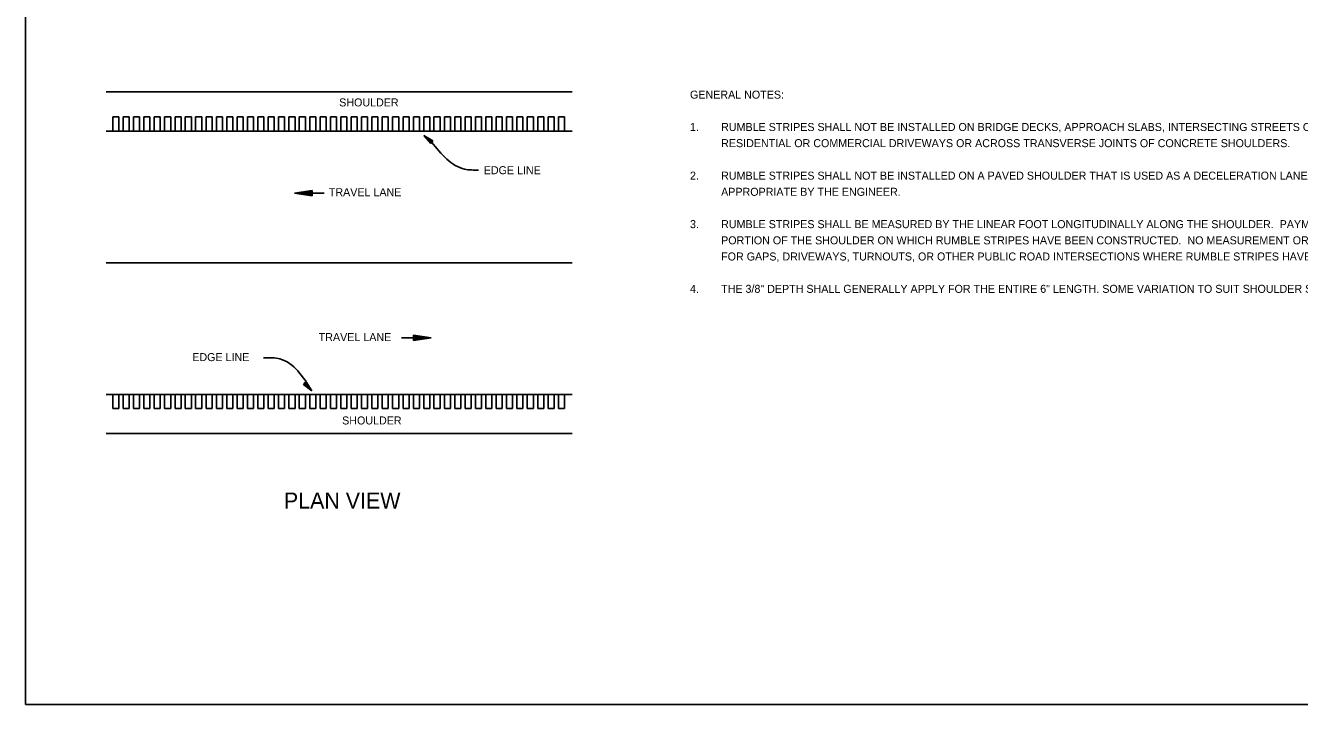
# Model space of a CAD drawing. Extents: x 28704 to 32542, y 50360 to 59122.
# Drawn here: x 28704 to 29736, y 50372 to 50922 of the extents above; entities that cross this region are included whole.
import ezdxf

# ---------------------------------------------------------------- set-up
doc = ezdxf.new("R2010")
doc.units = 0
doc.layers.add('Default', color=7, linetype='Continuous')

msp = doc.modelspace()

# ---------------------------------------------------------------- linework, layer by layer
at = {"layer": 'Default'}
for p, q in [((28769.2, 50868.5), (29146.9, 50868.5)), ((28774.7, 50836.8), (28774.7, 50848.3)), ((28774.7, 50848.3), (28779.6, 50848.3)), ((28779.6, 50836.8), (28779.6, 50848.3)), ((28783.1, 50836.8), (28783.1, 50848.3)), ((28783.1, 50848.3), (28788, 50848.3)), ((28788, 50836.8), (28788, 50848.3)), ((28791.5, 50836.8), (28791.5, 50848.3)), ((28791.5, 50848.3), (28796.4, 50848.3)), ((28796.4, 50836.8), (28796.4, 50848.3)), ((28799.9, 50836.8), (28799.9, 50848.3)), ((28799.9, 50848.3), (28804.8, 50848.3)), ((28804.8, 50836.8), (28804.8, 50848.3)), ((28808.3, 50836.8), (28808.3, 50848.3)), ((28808.3, 50848.3), (28813.2, 50848.3)), ((28813.2, 50836.8), (28813.2, 50848.3)), ((28816.7, 50836.8), (28816.7, 50848.3)), ((28816.7, 50848.3), (28821.6, 50848.3)), ((28821.6, 50836.8), (28821.6, 50848.3)), ((28825.1, 50836.8), (28825.1, 50848.3)), ((28825.1, 50848.3), (28830, 50848.3)), ((28830, 50836.8), (28830, 50848.3)), ((28833.4, 50836.8), (28833.4, 50848.3)), ((28833.4, 50848.3), (28838.4, 50848.3)), ((28838.4, 50836.8), (28838.4, 50848.3)), ((28841.8, 50836.8), (28841.8, 50848.3)), ((28841.8, 50848.3), (28846.8, 50848.3)), ((28846.8, 50836.8), (28846.8, 50848.3)), ((28850.2, 50836.8), (28850.2, 50848.3)), ((28850.2, 50848.3), (28855.2, 50848.3)), ((28855.2, 50836.8), (28855.2, 50848.3)), ((28858.6, 50836.8), (28858.6, 50848.3)), ((28858.6, 50848.3), (28863.5, 50848.3)), ((28863.5, 50836.8), (28863.5, 50848.3)), ((28867, 50836.8), (28867, 50848.3)), ((28867, 50848.3), (28871.9, 50848.3)), ((28871.9, 50836.8), (28871.9, 50848.3)), ((28875.4, 50836.8), (28875.4, 50848.3)), ((28875.4, 50848.3), (28880.3, 50848.3)), ((28880.3, 50836.8), (28880.3, 50848.3)), ((28883.8, 50836.8), (28883.8, 50848.3)), ((28883.8, 50848.3), (28888.7, 50848.3)), ((28888.7, 50836.8), (28888.7, 50848.3)), ((28892.2, 50836.8), (28892.2, 50848.3)), ((28892.2, 50848.3), (28897.1, 50848.3)), ((28897.1, 50836.8), (28897.1, 50848.3)), ((28900.6, 50836.8), (28900.6, 50848.3)), ((28900.6, 50836.8), (28900.6, 50848.3)), ((28900.6, 50848.3), (28905.5, 50848.3)), ((28905.5, 50836.8), (28905.5, 50848.3)), ((28909, 50836.8), (28909, 50848.3)), ((28909, 50848.3), (28913.9, 50848.3)), ((28913.9, 50836.8), (28913.9, 50848.3)), ((28917.4, 50836.8), (28917.4, 50848.3)), ((28917.4, 50848.3), (28922.3, 50848.3)), ((28922.3, 50836.8), (28922.3, 50848.3)), ((28925.8, 50836.8), (28925.8, 50848.3)), ((28925.8, 50848.3), (28930.7, 50848.3)), ((28930.7, 50836.8), (28930.7, 50848.3)), ((28934.2, 50836.8), (28934.2, 50848.3)), ((28934.2, 50848.3), (28939.1, 50848.3)), ((28939.1, 50836.8), (28939.1, 50848.3)), ((28942.6, 50836.8), (28942.6, 50848.3)), ((28942.6, 50848.3), (28947.5, 50848.3)), ((28947.5, 50836.8), (28947.5, 50848.3)), ((28951, 50836.8), (28951, 50848.3)), ((28951, 50848.3), (28955.9, 50848.3)), ((28955.9, 50836.8), (28955.9, 50848.3)), ((28959.4, 50836.8), (28959.4, 50848.3)), ((28959.4, 50848.3), (28964.3, 50848.3)), ((28964.3, 50836.8), (28964.3, 50848.3)), ((28967.8, 50836.8), (28967.8, 50848.3)), ((28967.8, 50848.3), (28972.7, 50848.3)), ((28972.7, 50836.8), (28972.7, 50848.3)), ((28976.2, 50836.8), (28976.2, 50848.3)), ((28976.2, 50848.3), (28981.1, 50848.3)), ((28981.1, 50836.8), (28981.1, 50848.3)), ((28984.6, 50836.8), (28984.6, 50848.3)), ((28984.6, 50848.3), (28989.5, 50848.3)), ((28989.5, 50836.8), (28989.5, 50848.3)), ((28993, 50836.8), (28993, 50848.3)), ((28993, 50848.3), (28997.9, 50848.3)), ((28997.9, 50836.8), (28997.9, 50848.3)), ((29001.4, 50836.8), (29001.4, 50848.3)), ((29001.4, 50848.3), (29006.3, 50848.3)), ((29006.3, 50836.8), (29006.3, 50848.3)), ((29009.8, 50836.8), (29009.8, 50848.3)), ((29009.8, 50848.3), (29014.7, 50848.3)), ((29014.7, 50836.8), (29014.7, 50848.3)), ((29018.2, 50836.8), (29018.2, 50848.3)), ((29018.2, 50848.3), (29023.1, 50848.3)), ((29023.1, 50836.8), (29023.1, 50848.3)), ((29026.6, 50836.8), (29026.6, 50848.3)), ((29026.6, 50848.3), (29031.5, 50848.3)), ((29031.5, 50836.8), (29031.5, 50848.3)), ((29034.9, 50836.8), (29034.9, 50848.3)), ((29034.9, 50848.3), (29039.9, 50848.3)), ((29039.9, 50836.8), (29039.9, 50848.3)), ((29043.3, 50836.8), (29043.3, 50848.3)), ((29043.3, 50848.3), (29048.3, 50848.3)), ((29048.3, 50836.8), (29048.3, 50848.3)), ((29051.7, 50836.8), (29051.7, 50848.3)), ((29051.7, 50848.3), (29056.7, 50848.3)), ((29056.7, 50836.8), (29056.7, 50848.3)), ((29060.1, 50836.8), (29060.1, 50848.3)), ((29060.1, 50848.3), (29065, 50848.3)), ((29065, 50836.8), (29065, 50848.3)), ((29068.5, 50836.8), (29068.5, 50848.3)), ((29068.5, 50848.3), (29073.4, 50848.3)), ((29073.4, 50836.8), (29073.4, 50848.3)), ((29076.9, 50836.8), (29076.9, 50848.3)), ((29076.9, 50848.3), (29081.8, 50848.3)), ((29081.8, 50836.8), (29081.8, 50848.3)), ((29085.3, 50836.8), (29085.3, 50848.3)), ((29085.3, 50848.3), (29090.2, 50848.3)), ((29090.2, 50836.8), (29090.2, 50848.3)), ((29093.7, 50836.8), (29093.7, 50848.3)), ((29093.7, 50848.3), (29098.6, 50848.3)), ((29098.6, 50836.8), (29098.6, 50848.3)), ((29102.1, 50836.8), (29102.1, 50848.3)), ((29102.1, 50848.3), (29107, 50848.3)), ((29107, 50836.8), (29107, 50848.3)), ((29110.5, 50836.8), (29110.5, 50848.3)), ((29110.5, 50848.3), (29115.4, 50848.3)), ((29115.4, 50836.8), (29115.4, 50848.3)), ((29118.9, 50836.8), (29118.9, 50848.3)), ((29118.9, 50848.3), (29123.8, 50848.3)), ((29123.8, 50836.8), (29123.8, 50848.3)), ((29127.3, 50836.8), (29127.3, 50848.3)), ((29127.3, 50848.3), (29132.2, 50848.3)), ((29132.2, 50836.8), (29132.2, 50848.3)), ((29135.7, 50836.8), (29135.7, 50848.3)), ((29135.7, 50848.3), (29140.6, 50848.3)), ((29140.6, 50836.8), (29140.6, 50848.3)), ((28769.2, 50836.8), (28957.2, 50836.8)), ((28779.6, 50836.8), (28774.7, 50836.8)), ((28788, 50836.8), (28783.1, 50836.8)), ((28796.4, 50836.8), (28791.5, 50836.8)), ((28804.8, 50836.8), (28799.9, 50836.8)), ((28813.2, 50836.8), (28808.3, 50836.8)), ((28821.6, 50836.8), (28816.7, 50836.8)), ((28830, 50836.8), (28825.1, 50836.8)), ((28838.4, 50836.8), (28833.4, 50836.8)), ((28846.8, 50836.8), (28841.8, 50836.8)), ((28855.2, 50836.8), (28850.2, 50836.8)), ((28863.5, 50836.8), (28858.6, 50836.8)), ((28871.9, 50836.8), (28867, 50836.8)), ((28880.3, 50836.8), (28875.4, 50836.8)), ((28888.7, 50836.8), (28883.8, 50836.8)), ((28897.1, 50836.8), (28892.2, 50836.8)), ((28905.5, 50836.8), (28900.6, 50836.8)), ((28913.9, 50836.8), (28909, 50836.8)), ((28922.3, 50836.8), (28917.4, 50836.8)), ((28930.7, 50836.8), (28925.8, 50836.8)), ((28939.1, 50836.8), (28934.2, 50836.8)), ((28947.5, 50836.8), (28942.6, 50836.8)), ((28955.9, 50836.8), (28951, 50836.8)), ((29146.9, 50836.8), (28957.2, 50836.8)), ((28964.3, 50836.8), (28959.4, 50836.8)), ((28972.7, 50836.8), (28967.8, 50836.8)), ((28981.1, 50836.8), (28976.2, 50836.8)), ((28989.5, 50836.8), (28984.6, 50836.8)), ((28997.9, 50836.8), (28993, 50836.8)), ((29006.3, 50836.8), (29001.4, 50836.8)), ((29014.7, 50836.8), (29009.8, 50836.8)), ((29023.1, 50836.8), (29018.2, 50836.8)), ((29031.5, 50836.8), (29026.6, 50836.8)), ((29032.4, 50826.8), (29026.7, 50833.3)), ((29034, 50828.9), (29026.7, 50833.3)), ((29032.6, 50827), (29027.8, 50832.3)), ((29033.9, 50828.7), (29027.8, 50832.3)), ((29039.9, 50836.8), (29034.9, 50836.8)), ((29048.3, 50836.8), (29043.3, 50836.8)), ((29056.7, 50836.8), (29051.7, 50836.8)), ((29065, 50836.8), (29060.1, 50836.8)), ((29073.4, 50836.8), (29068.5, 50836.8)), ((29081.8, 50836.8), (29076.9, 50836.8)), ((29090.2, 50836.8), (29085.3, 50836.8)), ((29098.6, 50836.8), (29093.7, 50836.8)), ((29107, 50836.8), (29102.1, 50836.8)), ((29115.4, 50836.8), (29110.5, 50836.8)), ((29123.8, 50836.8), (29118.9, 50836.8)), ((29132.2, 50836.8), (29127.3, 50836.8)), ((29140.6, 50836.8), (29135.7, 50836.8)), ((29033.8, 50828.5), (29028.9, 50831.4)), ((29032.7, 50827.2), (29028.9, 50831.4)), ((29032.8, 50827.4), (29030, 50830.5)), ((29033.6, 50828.4), (29030, 50830.5)), ((29033.5, 50828.2), (29031.1, 50829.6)), ((29033, 50827.5), (29031.1, 50829.6)), ((29033.4, 50828), (29032.2, 50828.7)), ((29033.1, 50827.7), (29032.2, 50828.7)), ((29032.4, 50826.8), (29034, 50828.9)), ((28936.1, 50788.7), (28922, 50786.5)), ((28946, 50786.5), (28922, 50786.5)), ((28936.1, 50784.3), (28922, 50786.5)), ((28936.1, 50788.3), (28924.4, 50786.5)), ((28936.1, 50784.7), (28924.4, 50786.5)), ((28936.1, 50788), (28926.8, 50786.5)), ((28936.1, 50785.1), (28926.8, 50786.5)), ((28936.1, 50787.6), (28929.1, 50786.5)), ((28936.1, 50785.4), (28929.1, 50786.5)), ((28936.1, 50787.2), (28931.5, 50786.5)), ((28936.1, 50785.8), (28931.5, 50786.5)), ((28936.1, 50786.9), (28933.9, 50786.5)), ((28936.1, 50786.2), (28933.9, 50786.5)), ((28936.1, 50788.7), (28936.1, 50784.3)), ((28769.2, 50730.2), (29146.9, 50730.2)), ((29008.5, 50669.4), (29032.6, 50669.4)), ((29018.4, 50671.6), (29032.6, 50669.4)), ((29018.4, 50667.3), (29018.4, 50671.6)), ((29018.4, 50671.2), (29030.2, 50669.4)), ((29018.4, 50670.9), (29027.8, 50669.4)), ((29018.4, 50670.5), (29025.5, 50669.4)), ((29018.4, 50670.1), (29023, 50669.4)), ((29018.4, 50669.8), (29020.7, 50669.4)), ((29018.4, 50667.3), (29032.6, 50669.4)), ((29018.4, 50668.7), (29023, 50669.4)), ((29018.4, 50668), (29027.8, 50669.4)), ((29018.4, 50667.6), (29030.2, 50669.4)), ((29018.4, 50668.3), (29025.5, 50669.4)), ((29018.4, 50669.1), (29020.7, 50669.4)), ((28930.8, 50633.4), (28929.1, 50631.6)), ((28929.1, 50631.6), (28936, 50626.5)), ((28929.2, 50631.7), (28935, 50627.5)), ((28929.4, 50631.9), (28933.9, 50628.5)), ((28929.5, 50632), (28933, 50629.5)), ((28929.7, 50632.2), (28931.9, 50630.5)), ((28929.8, 50632.4), (28930.9, 50631.6)), ((28930.1, 50632.6), (28930.9, 50631.6)), ((28930.3, 50632.8), (28931.9, 50630.5)), ((28930.4, 50633), (28933, 50629.5)), ((28930.5, 50633.1), (28933.9, 50628.5)), ((28930.7, 50633.3), (28935, 50627.5)), ((28930.8, 50633.4), (28936, 50626.5)), ((28769.2, 50623.5), (28957.2, 50623.5)), ((28779.6, 50623.5), (28774.7, 50623.5)), ((28774.7, 50623.5), (28774.7, 50612)), ((28779.6, 50623.5), (28779.6, 50612)), ((28788, 50623.5), (28783.1, 50623.5)), ((28783.1, 50623.5), (28783.1, 50612)), ((28788, 50623.5), (28788, 50612)), ((28796.4, 50623.5), (28791.5, 50623.5)), ((28791.5, 50623.5), (28791.5, 50612)), ((28796.4, 50623.5), (28796.4, 50612)), ((28804.8, 50623.5), (28799.9, 50623.5)), ((28799.9, 50623.5), (28799.9, 50612)), ((28804.8, 50623.5), (28804.8, 50612)), ((28813.2, 50623.5), (28808.3, 50623.5)), ((28808.3, 50623.5), (28808.3, 50612)), ((28813.2, 50623.5), (28813.2, 50612)), ((28821.6, 50623.5), (28816.7, 50623.5)), ((28816.7, 50623.5), (28816.7, 50612)), ((28821.6, 50623.5), (28821.6, 50612)), ((28830, 50623.5), (28825.1, 50623.5)), ((28825.1, 50623.5), (28825.1, 50612)), ((28830, 50623.5), (28830, 50612)), ((28838.4, 50623.5), (28833.4, 50623.5)), ((28833.4, 50623.5), (28833.4, 50612)), ((28838.4, 50623.5), (28838.4, 50612)), ((28846.8, 50623.5), (28841.8, 50623.5)), ((28841.8, 50623.5), (28841.8, 50612)), ((28846.8, 50623.5), (28846.8, 50612)), ((28855.2, 50623.5), (28850.2, 50623.5)), ((28850.2, 50623.5), (28850.2, 50612)), ((28855.2, 50623.5), (28855.2, 50612)), ((28863.5, 50623.5), (28858.6, 50623.5)), ((28858.6, 50623.5), (28858.6, 50612)), ((28863.5, 50623.5), (28863.5, 50612)), ((28871.9, 50623.5), (28867, 50623.5)), ((28867, 50623.5), (28867, 50612)), ((28871.9, 50623.5), (28871.9, 50612)), ((28880.3, 50623.5), (28875.4, 50623.5)), ((28875.4, 50623.5), (28875.4, 50612)), ((28880.3, 50623.5), (28880.3, 50612)), ((28888.7, 50623.5), (28883.8, 50623.5)), ((28883.8, 50623.5), (28883.8, 50612)), ((28888.7, 50623.5), (28888.7, 50612)), ((28897.1, 50623.5), (28892.2, 50623.5)), ((28892.2, 50623.5), (28892.2, 50612)), ((28897.1, 50623.5), (28897.1, 50612)), ((28905.5, 50623.5), (28900.6, 50623.5)), ((28900.6, 50623.5), (28900.6, 50612)), ((28905.5, 50623.5), (28905.5, 50612)), ((28913.9, 50623.5), (28909, 50623.5)), ((28909, 50623.5), (28909, 50612)), ((28913.9, 50623.5), (28913.9, 50612)), ((28922.3, 50623.5), (28917.4, 50623.5)), ((28917.4, 50623.5), (28917.4, 50612)), ((28922.3, 50623.5), (28922.3, 50612)), ((28930.7, 50623.5), (28925.8, 50623.5)), ((28925.8, 50623.5), (28925.8, 50612)), ((28930.7, 50623.5), (28930.7, 50612)), ((28939.1, 50623.5), (28934.2, 50623.5)), ((28934.2, 50623.5), (28934.2, 50612)), ((28939.1, 50623.5), (28939.1, 50612)), ((28947.5, 50623.5), (28942.6, 50623.5)), ((28942.6, 50623.5), (28942.6, 50612)), ((28947.5, 50623.5), (28947.5, 50612)), ((28955.9, 50623.5), (28951, 50623.5)), ((28951, 50623.5), (28951, 50612)), ((28955.9, 50623.5), (28955.9, 50612)), ((29146.9, 50623.5), (28957.2, 50623.5)), ((28964.3, 50623.5), (28959.4, 50623.5)), ((28959.4, 50623.5), (28959.4, 50612)), ((28964.3, 50623.5), (28964.3, 50612)), ((28972.7, 50623.5), (28967.8, 50623.5)), ((28967.8, 50623.5), (28967.8, 50612)), ((28972.7, 50623.5), (28972.7, 50612)), ((28981.1, 50623.5), (28976.2, 50623.5)), ((28976.2, 50623.5), (28976.2, 50612)), ((28981.1, 50623.5), (28981.1, 50612)), ((28989.5, 50623.5), (28984.6, 50623.5)), ((28984.6, 50623.5), (28984.6, 50612)), ((28989.5, 50623.5), (28989.5, 50612)), ((28997.9, 50623.5), (28993, 50623.5)), ((28993, 50623.5), (28993, 50612)), ((28997.9, 50623.5), (28997.9, 50612)), ((29006.3, 50623.5), (29001.4, 50623.5)), ((29001.4, 50623.5), (29001.4, 50612)), ((29006.3, 50623.5), (29006.3, 50612)), ((29014.7, 50623.5), (29009.8, 50623.5)), ((29009.8, 50623.5), (29009.8, 50612)), ((29014.7, 50623.5), (29014.7, 50612)), ((29023.1, 50623.5), (29018.2, 50623.5)), ((29018.2, 50623.5), (29018.2, 50612)), ((29023.1, 50623.5), (29023.1, 50612)), ((29031.5, 50623.5), (29026.6, 50623.5)), ((29026.6, 50623.5), (29026.6, 50612)), ((29031.5, 50623.5), (29031.5, 50612)), ((29039.9, 50623.5), (29034.9, 50623.5)), ((29034.9, 50623.5), (29034.9, 50612)), ((29039.9, 50623.5), (29039.9, 50612)), ((29048.3, 50623.5), (29043.3, 50623.5)), ((29043.3, 50623.5), (29043.3, 50612)), ((29048.3, 50623.5), (29048.3, 50612)), ((29056.7, 50623.5), (29051.7, 50623.5)), ((29051.7, 50623.5), (29051.7, 50612)), ((29056.7, 50623.5), (29056.7, 50612)), ((29065, 50623.5), (29060.1, 50623.5)), ((29060.1, 50623.5), (29060.1, 50612)), ((29065, 50623.5), (29065, 50612)), ((29073.4, 50623.5), (29068.5, 50623.5)), ((29068.5, 50623.5), (29068.5, 50612)), ((29073.4, 50623.5), (29073.4, 50612)), ((29081.8, 50623.5), (29076.9, 50623.5)), ((29076.9, 50623.5), (29076.9, 50612)), ((29081.8, 50623.5), (29081.8, 50612)), ((29090.2, 50623.5), (29085.3, 50623.5)), ((29085.3, 50623.5), (29085.3, 50612)), ((29090.2, 50623.5), (29090.2, 50612)), ((29098.6, 50623.5), (29093.7, 50623.5)), ((29093.7, 50623.5), (29093.7, 50612)), ((29098.6, 50623.5), (29098.6, 50612)), ((29107, 50623.5), (29102.1, 50623.5)), ((29102.1, 50623.5), (29102.1, 50612)), ((29107, 50623.5), (29107, 50612)), ((29115.4, 50623.5), (29110.5, 50623.5)), ((29110.5, 50623.5), (29110.5, 50612)), ((29115.4, 50623.5), (29115.4, 50612)), ((29123.8, 50623.5), (29118.9, 50623.5)), ((29118.9, 50623.5), (29118.9, 50612)), ((29123.8, 50623.5), (29123.8, 50612)), ((29132.2, 50623.5), (29127.3, 50623.5)), ((29127.3, 50623.5), (29127.3, 50612)), ((29132.2, 50623.5), (29132.2, 50612)), ((29140.6, 50623.5), (29135.7, 50623.5)), ((29135.7, 50623.5), (29135.7, 50612)), ((29140.6, 50623.5), (29140.6, 50612)), ((28774.7, 50612), (28779.6, 50612)), ((28783.1, 50612), (28788, 50612)), ((28791.5, 50612), (28796.4, 50612)), ((28799.9, 50612), (28804.8, 50612)), ((28808.3, 50612), (28813.2, 50612)), ((28816.7, 50612), (28821.6, 50612)), ((28825.1, 50612), (28830, 50612)), ((28833.4, 50612), (28838.4, 50612)), ((28841.8, 50612), (28846.8, 50612)), ((28850.2, 50612), (28855.2, 50612)), ((28858.6, 50612), (28863.5, 50612)), ((28867, 50612), (28871.9, 50612)), ((28875.4, 50612), (28880.3, 50612)), ((28883.8, 50612), (28888.7, 50612)), ((28892.2, 50612), (28897.1, 50612)), ((28900.6, 50612), (28905.5, 50612)), ((28909, 50612), (28913.9, 50612)), ((28917.4, 50612), (28922.3, 50612)), ((28925.8, 50612), (28930.7, 50612)), ((28934.2, 50612), (28939.1, 50612)), ((28942.6, 50612), (28947.5, 50612)), ((28951, 50612), (28955.9, 50612)), ((28959.4, 50612), (28964.3, 50612)), ((28967.8, 50612), (28972.7, 50612)), ((28976.2, 50612), (28981.1, 50612)), ((28984.6, 50612), (28989.5, 50612)), ((28993, 50612), (28997.9, 50612)), ((29001.4, 50612), (29006.3, 50612)), ((29009.8, 50612), (29014.7, 50612)), ((29018.2, 50612), (29023.1, 50612)), ((29026.6, 50612), (29031.5, 50612)), ((29034.9, 50612), (29039.9, 50612)), ((29043.3, 50612), (29048.3, 50612)), ((29051.7, 50612), (29056.7, 50612)), ((29060.1, 50612), (29065, 50612)), ((29068.5, 50612), (29073.4, 50612)), ((29076.9, 50612), (29081.8, 50612)), ((29085.3, 50612), (29090.2, 50612)), ((29093.7, 50612), (29098.6, 50612)), ((29102.1, 50612), (29107, 50612)), ((29110.5, 50612), (29115.4, 50612)), ((29118.9, 50612), (29123.8, 50612)), ((29127.3, 50612), (29132.2, 50612)), ((29135.7, 50612), (29140.6, 50612)), ((28769.2, 50591.8), (29146.9, 50591.8))]:
    msp.add_line(p, q, dxfattribs=at)
for points in [[(28704, 51472.4), (30404, 51472.4), (30404, 50372.4), (28704, 50372.4)], [(28704, 51472.4), (28704, 50372.4), (30404, 50372.4), (30404, 51472.4)]]:
    msp.add_lwpolyline(points, close=True, dxfattribs=at)
for points in [[(29071, 50805.2), (29059.7, 50806), (29032.9, 50827.9)], [(28896.8, 50653.2), (28910.1, 50652.3), (28936, 50626.5)]]:
    msp.add_spline(points, degree=3, dxfattribs=at)

# ---------------------------------------------------------------- texts
for s, height, p in [('SHOULDER', 6.48, (28958.1, 50856.8)), ('GENERAL NOTES:', 6.485, (29242.3, 50863.1)), ('1.', 6.48, (29242.3, 50836.9)), ('RUMBLE STRIPES SHALL NOT BE INSTALLED ON BRIDGE DECKS, APPROACH SLABS, INTERSECTING STREETS OR ROADWAYS,', 6.485, (29267.5, 50836.9)), ('RESIDENTIAL OR COMMERCIAL DRIVEWAYS OR ACROSS TRANSVERSE JOINTS OF CONCRETE SHOULDERS.', 6.485, (29267.5, 50823.8)), ('EDGE LINE', 6.48, (29075.2, 50801.9)), ('2.', 6.48, (29242.3, 50797.5)), ('RUMBLE STRIPES SHALL NOT BE INSTALLED ON A PAVED SHOULDER THAT IS USED AS A DECELERATION LANE FOR THE LENGTH DEEMED', 6.485, (29267.5, 50797.5)), ('TRAVEL LANE', 6.485, (28949.7, 50784.1)), ('APPROPRIATE BY THE ENGINEER.', 6.485, (29267.5, 50784.4)), ('3.', 6.48, (29242.3, 50758.2)), ('RUMBLE STRIPES SHALL BE MEASURED BY THE LINEAR FOOT LONGITUDINALLY ALONG THE SHOULDER.  PAYMENT SHALL ONLY INCLUDE THAT', 6.485, (29267.5, 50758.2)), ('PORTION OF THE SHOULDER ON WHICH RUMBLE STRIPES HAVE BEEN CONSTRUCTED.  NO MEASUREMENT OR PAYMENT WILL BE MADE', 6.485, (29267.5, 50745.1)), ('FOR GAPS, DRIVEWAYS, TURNOUTS, OR OTHER PUBLIC ROAD INTERSECTIONS WHERE RUMBLE STRIPES HAVE NOT BEEN CONSTRUCTED.', 6.485, (29267.5, 50732)), ('4.', 6.48, (29242.3, 50705.8)), ('THE 3/8" DEPTH SHALL GENERALLY APPLY FOR THE ENTIRE 6" LENGTH. SOME VARIATION TO SUIT SHOULDER SLOPE BREAKS MAY BE NECESSARY.', 6.485, (29267.5, 50705.8)), ('TRAVEL LANE', 6.485, (28941.5, 50666.7)), ('EDGE LINE', 6.48, (28839.1, 50650.5)), ('SHOULDER', 6.48, (28960.5, 50599.2)), ('PLAN VIEW ', 12.97, (28913.3, 50531.1))]:
    msp.add_text(s, height=height, dxfattribs=at).set_placement(p)

doc.saveas('drawing.dxf')
